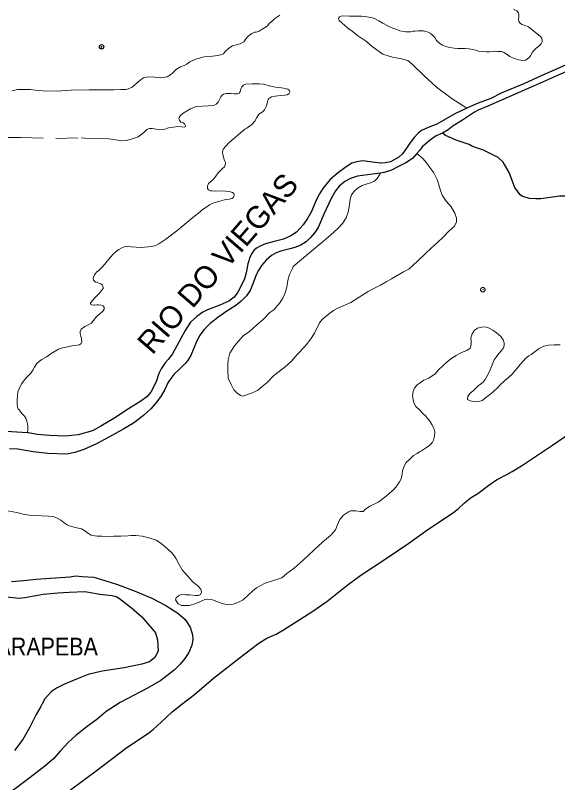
# Model space of a CAD drawing. Extents: x 267.7 to 296, y 7537.7 to 7565.8.
# Drawn here: x 280.408 to 282.842, y 7555.949 to 7559.393 of the extents above; entities that cross this region are included whole.
import ezdxf
from ezdxf.enums import TextEntityAlignment as Align

# ---------------------------------------------------------------- set-up
doc = ezdxf.new("R2010")
doc.units = 0
doc.header["$LTSCALE"] = 0.04
doc.header["$PDMODE"] = 32
doc.header["$PDSIZE"] = 0.02
doc.linetypes.add('SHORT_DASHED', pattern=[2.7, 1.5, -1.2])
for name, color, linetype, lineweight in [('1', 7, 'Continuous', 25), ('2', 7, 'Continuous', 25), ('21', 7, 'SHORT_DASHED', 13), ('7', 7, 'Continuous', 25)]:
    doc.layers.add(name, color=color, linetype=linetype, lineweight=lineweight)
doc.layers.add('54', color=7, linetype='Continuous')
doc.layers.add('61', color=7, linetype='Continuous')

msp = doc.modelspace()

# ---------------------------------------------------------------- linework, layer by layer
at = {"layer": '1'}
for points in [[(284.4547, 7559.8523), (284.377, 7559.8218), (284.2867, 7559.7831), (284.1184, 7559.7122), (283.9591, 7559.6438), (283.6289, 7559.4987), (283.5547, 7559.465), (283.1514, 7559.2873), (283.0583, 7559.2484), (282.7675, 7559.1216), (282.6934, 7559.0875), (282.5888, 7559.0438), (282.5414, 7559.0202), (282.4852, 7558.9986), (282.4399, 7558.9791), (282.4346, 7558.9766)], [(284.4569, 7559.8141), (284.4466, 7559.8195), (284.4404, 7559.8202), (284.422, 7559.8154), (284.324, 7559.7695), (284.0384, 7559.6483), (283.9549, 7559.6106), (283.5617, 7559.4394), (283.3631, 7559.3504), (282.9624, 7559.1771), (282.7741, 7559.0929), (282.5289, 7558.986), (282.4844, 7558.9668), (282.4686, 7558.9579), (282.4549, 7558.949), (282.4152, 7558.9223), (282.3734, 7558.8977), (282.3501, 7558.8792), (282.3251, 7558.8643)], [(282.4346, 7558.9766), (282.381, 7558.9507), (282.299, 7558.905), (282.2606, 7558.8897), (282.2301, 7558.8755), (282.2159, 7558.8645), (282.1981, 7558.8445), (282.1781, 7558.8188), (282.1633, 7558.7967), (282.146, 7558.772), (282.1292, 7558.7572), (282.105, 7558.7425), (282.0913, 7558.7362), (282.0682, 7558.7304), (282.0492, 7558.7294), (282.0466, 7558.7297)], [(282.3251, 7558.8643), (282.296, 7558.8525), (282.2714, 7558.8347), (282.2337, 7558.8025), (282.2227, 7558.7881), (282.2101, 7558.7735)], [(282.2101, 7558.7735), (282.1906, 7558.7511), (282.1611, 7558.7312), (282.1275, 7558.7141), (282.0954, 7558.6977), (282.0639, 7558.6881), (282.0608, 7558.6876)]]:
    msp.add_lwpolyline(points, dxfattribs=at)
at = {"layer": '2'}
msp.add_line((282.0608, 7558.6876), (282.0465, 7558.6854), dxfattribs=at)
for points in [[(282.0466, 7558.7297), (282.0208, 7558.7325), (281.9672, 7558.7399), (281.9404, 7558.7362), (281.9188, 7558.7294), (281.892, 7558.7131), (281.852, 7558.6826), (281.8189, 7558.6552), (281.7874, 7558.6163), (281.7726, 7558.5926), (281.7584, 7558.5637), (281.7369, 7558.5127), (281.719, 7558.4812), (281.6996, 7558.4533), (281.6701, 7558.4202), (281.6449, 7558.4033), (281.6117, 7558.3886), (281.5697, 7558.3776), (281.5302, 7558.3676), (281.5071, 7558.3576), (281.4903, 7558.3481), (281.4782, 7558.3371), (281.4687, 7558.3245), (281.4619, 7558.3108), (281.4519, 7558.2777), (281.444, 7558.2372), (281.4366, 7558.2109), (281.4256, 7558.1877), (281.4061, 7558.1504), (281.3893, 7558.1288), (281.3656, 7558.1104), (281.3262, 7558.092), (281.271, 7558.0715), (281.2489, 7558.0605), (281.2226, 7558.0416), (281.1947, 7558.0153), (281.1706, 7557.979), (281.1527, 7557.9459), (281.1127, 7557.8743), (281.0933, 7557.8486), (281.0801, 7557.8328), (281.0617, 7557.806), (281.0522, 7557.7849), (281.0417, 7557.7529), (281.0296, 7557.7266), (281.0165, 7557.7019), (280.9981, 7557.6814), (280.9707, 7557.6614), (280.915, 7557.6261), (280.8498, 7557.583), (280.7919, 7557.5494), (280.7536, 7557.5278), (280.6899, 7557.5099), (280.6337, 7557.5047), (280.5606, 7557.5068), (280.5064, 7557.512), (280.4671, 7557.5189), (280.4627, 7557.5192)], [(282.0465, 7558.6854), (282.0104, 7558.6799), (281.944, 7558.6716), (281.9125, 7558.6607), (281.8871, 7558.647), (281.8611, 7558.6264), (281.8454, 7558.6059), (281.8248, 7558.5703), (281.7919, 7558.5011), (281.7673, 7558.4415), (281.7522, 7558.4182), (281.733, 7558.3956), (281.7125, 7558.3765), (281.6892, 7558.3614), (281.6625, 7558.3504), (281.6392, 7558.3456), (281.6036, 7558.3367), (281.5783, 7558.3271), (281.557, 7558.3155), (281.5337, 7558.2936), (281.5146, 7558.2717), (281.5002, 7558.2504), (281.4892, 7558.2278), (281.4769, 7558.195), (281.4618, 7558.1573), (281.4447, 7558.134), (281.4214, 7558.11), (281.3974, 7558.0909), (281.3577, 7558.0655), (281.3166, 7558.0374), (281.2824, 7558.01), (281.2536, 7557.9813), (281.2379, 7557.9587), (281.2228, 7557.932), (281.2091, 7557.8991), (281.1954, 7557.8669), (281.181, 7557.8416), (281.1707, 7557.8306), (281.1454, 7557.8059), (281.1187, 7557.7806), (281.1057, 7557.7635), (281.092, 7557.7429), (281.0783, 7557.7135), (281.0618, 7557.6854), (281.0434, 7557.658), (281.0153, 7557.6272), (280.9824, 7557.597), (280.9386, 7557.5621), (280.8954, 7557.5368), (280.8475, 7557.5107), (280.7728, 7557.4697), (280.716, 7557.445), (280.6742, 7557.4306), (280.6393, 7557.4238), (280.553, 7557.4258), (280.4872, 7557.434), (280.4187, 7557.4457), (280.3811, 7557.4477)], [(280.6026, 7555.8775), (280.7073, 7555.9548), (280.7711, 7556.0022), (280.908, 7556.1063), (281.0057, 7556.1707), (281.0286, 7556.1888), (281.0608, 7556.2181), (281.1111, 7556.2667), (281.1544, 7556.3012), (281.2123, 7556.3439), (281.2978, 7556.4171), (281.4324, 7556.5218), (281.5014, 7556.5751), (281.5371, 7556.5967), (281.5786, 7556.6149), (281.6108, 7556.6353), (281.7384, 7556.7161), (281.8063, 7556.7623), (281.8952, 7556.8343), (281.9578, 7556.8794), (282.072, 7556.9554), (282.1732, 7557.0245), (282.2598, 7557.0848), (282.3704, 7557.1579), (282.3956, 7557.1772), (282.4237, 7557.2041), (282.4541, 7557.2287), (282.4833, 7557.2463), (282.5325, 7557.2849), (282.5676, 7557.3083), (282.6133, 7557.3323), (282.6378, 7557.3452), (282.6794, 7557.3703), (282.8181, 7557.464), (283.0802, 7557.643)], [(280.4627, 7557.5192), (280.3899, 7557.5242), (280.3547, 7557.5253), (280.3201, 7557.5194), (280.287, 7557.5093), (280.2588, 7557.4933), (280.2322, 7557.4741), (280.2055, 7557.4464), (280.165, 7557.3889), (280.1086, 7557.3074), (280.0956, 7557.2871), (280.0755, 7557.2557)], [(280.3913, 7556.8522), (280.4447, 7556.856), (280.5009, 7556.8616), (280.6527, 7556.8729), (280.6799, 7556.8766), (280.708, 7556.8747), (280.7595, 7556.871), (280.8092, 7556.8569), (280.8663, 7556.8382), (280.946, 7556.8082), (281.0209, 7556.7764), (281.0828, 7556.7445), (281.1371, 7556.7098), (281.1699, 7556.6817), (281.1924, 7556.6461), (281.2036, 7556.6124), (281.2045, 7556.5918), (281.1999, 7556.5656), (281.1867, 7556.5337), (281.1689, 7556.5065), (281.1474, 7556.4812), (281.1212, 7556.4541), (281.0603, 7556.4072), (281.0003, 7556.3726), (280.8785, 7556.3079), (280.8148, 7556.2676), (280.7736, 7556.232), (280.7295, 7556.2002), (280.679, 7556.1599), (280.6471, 7556.1308), (280.6087, 7556.0906), (280.5787, 7556.055), (280.5403, 7556.0222), (280.4747, 7555.9725), (280.3792, 7555.8994)], [(280.3677, 7556.7835), (280.424, 7556.7774), (280.4501, 7556.7804), (280.5334, 7556.7945), (280.5987, 7556.8005), (280.6489, 7556.8035), (280.7192, 7556.8066), (280.7544, 7556.8015), (280.7875, 7556.7955), (280.8136, 7556.7925), (280.8428, 7556.7885), (280.8598, 7556.7845), (280.8749, 7556.7754), (280.9291, 7556.7342), (280.9753, 7556.6931), (281.0115, 7556.6519), (281.0296, 7556.6308), (281.0366, 7556.6208), (281.0456, 7556.5906), (281.0486, 7556.5384), (281.0346, 7556.5103), (281.0105, 7556.4912), (280.9763, 7556.4802), (280.897, 7556.4641), (280.7976, 7556.449), (280.7343, 7556.434), (280.6831, 7556.4129), (280.6288, 7556.3908), (280.5927, 7556.3727), (280.5706, 7556.3576), (280.5545, 7556.3416), (280.5405, 7556.3245), (280.5284, 7556.3024), (280.5224, 7556.2913), (280.5013, 7556.2542), (280.4732, 7556.1979), (280.442, 7556.1427), (280.4039, 7556.0925)]]:
    msp.add_lwpolyline(points, dxfattribs=at)
at = {"layer": '21'}
for points in [[(280.3935, 7559.0548), (280.4182, 7559.06), (280.4466, 7559.0609), (280.4741, 7559.0604), (280.4964, 7559.0576), (280.5291, 7559.0548), (280.5945, 7559.0533), (280.658, 7559.0567), (280.7386, 7559.0585), (280.7869, 7559.0581), (280.8239, 7559.0581), (280.8495, 7559.0595), (280.8808, 7559.06), (280.905, 7559.0609), (280.9182, 7559.0647), (280.9315, 7559.0709), (280.9415, 7559.0789), (280.9576, 7559.0932), (280.9737, 7559.1064), (280.9837, 7559.1121), (281.0045, 7559.1164), (281.0329, 7559.1159), (281.0595, 7559.1121), (281.0894, 7559.1169), (281.1045, 7559.1254), (281.1145, 7559.1344), (281.1315, 7559.151), (281.1486, 7559.1619), (281.1661, 7559.168), (281.1775, 7559.1733), (281.1908, 7559.1842), (281.2079, 7559.1922), (281.2178, 7559.197), (281.2548, 7559.2064), (281.2927, 7559.2102), (281.3164, 7559.2126), (281.3344, 7559.2169), (281.3415, 7559.2211), (281.3491, 7559.2306), (281.3662, 7559.2458), (281.3832, 7559.2567), (281.4055, 7559.2619), (281.4169, 7559.2647), (281.434, 7559.2737), (281.4401, 7559.2828), (281.4496, 7559.296), (281.4581, 7559.3046), (281.4686, 7559.3121), (281.4818, 7559.3174), (281.4894, 7559.3183), (281.5022, 7559.3221), (281.5155, 7559.3316), (281.5382, 7559.3453), (281.5491, 7559.3576), (281.5619, 7559.369), (281.5724, 7559.3794), (281.5956, 7559.3941)], [(282.4346, 7558.9766), (282.369, 7559.0187), (282.2981, 7559.0713), (282.2422, 7559.1221), (282.1885, 7559.1746), (282.169, 7559.1901), (282.1411, 7559.1981), (282.1005, 7559.2049), (282.0851, 7559.2106), (282.0571, 7559.2186), (282.0417, 7559.2289), (282.0091, 7559.2529), (281.98, 7559.2786), (281.9428, 7559.3032), (281.92, 7559.3226), (281.9, 7559.3357), (281.8863, 7559.3472), (281.8737, 7559.3591), (281.8612, 7559.3694), (281.86, 7559.3734), (281.8589, 7559.3791), (281.86, 7559.3826), (281.8634, 7559.3871), (281.8703, 7559.3894), (281.8772, 7559.3906), (281.908, 7559.39), (281.9617, 7559.39), (281.9857, 7559.3871), (282.004, 7559.3837), (282.0205, 7559.3791), (282.04, 7559.3689), (282.0577, 7559.3574), (282.0851, 7559.3432), (282.1028, 7559.3357), (282.1205, 7559.3289), (282.1331, 7559.3243), (282.1496, 7559.3209), (282.1605, 7559.3197), (282.1719, 7559.3197), (282.1822, 7559.3197), (282.193, 7559.322), (282.2028, 7559.3226), (282.2147, 7559.3232), (282.2399, 7559.3237), (282.2564, 7559.3197), (282.2702, 7559.3129), (282.2822, 7559.3026), (282.2901, 7559.294), (282.2987, 7559.2797), (282.313, 7559.2672), (282.3244, 7559.2598), (282.3398, 7559.2535), (282.3587, 7559.2483), (282.3775, 7559.2455), (282.3935, 7559.2443), (282.4141, 7559.2443), (282.4272, 7559.2438), (282.4432, 7559.2426), (282.4615, 7559.2403), (282.4747, 7559.2363), (282.4866, 7559.2323), (282.5032, 7559.2306), (282.5204, 7559.2301), (282.5358, 7559.2295), (282.5518, 7559.2306), (282.5649, 7559.2318), (282.574, 7559.2306), (282.5895, 7559.2306), (282.6003, 7559.2266), (282.6152, 7559.2169), (282.6277, 7559.2078), (282.646, 7559.1998), (282.6683, 7559.1929), (282.6849, 7559.1906), (282.6974, 7559.1923), (282.7054, 7559.1963), (282.714, 7559.2032), (282.7203, 7559.2112), (282.7294, 7559.2272), (282.7357, 7559.2358), (282.7448, 7559.2455), (282.7574, 7559.2552), (282.7677, 7559.266), (282.7717, 7559.274), (282.7723, 7559.2797), (282.7705, 7559.2906), (282.7654, 7559.2975), (282.7408, 7559.3174), (282.7203, 7559.334), (282.7117, 7559.3409), (282.6951, 7559.3477), (282.6809, 7559.3523), (282.6734, 7559.3574), (282.6672, 7559.3654), (282.6654, 7559.3751)], [(282.6654, 7559.3751), (282.6672, 7559.3866), (282.6683, 7559.3951), (282.666, 7559.4048), (282.658, 7559.4134), (282.6443, 7559.4214)], [(280.3509, 7558.8446), (280.4331, 7558.8451), (280.5894, 7558.8402), (280.704, 7558.8435), (280.7358, 7558.8402), (280.8257, 7558.8391), (280.8684, 7558.8331), (280.8865, 7558.8303), (280.9052, 7558.8314), (280.9227, 7558.8364), (280.9589, 7558.8473), (280.971, 7558.8567), (280.9847, 7558.8676), (280.9973, 7558.8813), (281.0093, 7558.8852), (281.0225, 7558.8852), (281.04, 7558.8824), (281.0696, 7558.8808), (281.079, 7558.8819), (281.0954, 7558.8879), (281.1173, 7558.8917), (281.1371, 7558.8939), (281.1541, 7558.8923), (281.1656, 7558.8906), (281.1705, 7558.8934), (281.1716, 7558.8978), (281.1672, 7558.9055), (281.1607, 7558.9109), (281.1513, 7558.9142), (281.1442, 7558.9219), (281.142, 7558.9285), (281.1437, 7558.9345), (281.148, 7558.9427), (281.1612, 7558.9537), (281.1766, 7558.9625), (281.1941, 7558.9734), (281.2193, 7558.9833), (281.2473, 7558.986), (281.2983, 7558.9882), (281.3098, 7558.9948), (281.3185, 7559.0041), (281.324, 7559.0151), (281.3295, 7559.0272), (281.3344, 7559.0337), (281.3416, 7559.0387), (281.3547, 7559.042), (281.3745, 7559.0425), (281.3898, 7559.0414), (281.4052, 7559.0409), (281.4117, 7559.0431), (281.4167, 7559.0502), (281.4178, 7559.0573), (281.4194, 7559.0639), (281.4244, 7559.0727), (281.4326, 7559.0803), (281.4424, 7559.0842), (281.4726, 7559.0858), (281.5022, 7559.0858), (281.5219, 7559.0836), (281.5378, 7559.0803), (281.5472, 7559.076), (281.5757, 7559.0705), (281.5899, 7559.0699), (281.6025, 7559.0683), (281.6201, 7559.065), (281.631, 7559.0622), (281.6376, 7559.0562), (281.6393, 7559.0502), (281.6354, 7559.0414), (281.6283, 7559.0365), (281.6157, 7559.0343), (281.5981, 7559.0332), (281.5746, 7559.0304), (281.557, 7559.0272), (281.5444, 7559.0178), (281.5395, 7559.0069), (281.5346, 7558.9871), (281.5263, 7558.9696), (281.5159, 7558.9581), (281.5011, 7558.9499), (281.4912, 7558.9351), (281.4825, 7558.9181)], [(281.4825, 7558.9181), (281.4688, 7558.9027), (281.4474, 7558.8868), (281.4375, 7558.8819), (281.3657, 7558.8216), (281.341, 7558.7925)], [(281.341, 7558.7925), (281.3388, 7558.7859), (281.3377, 7558.7783), (281.3394, 7558.7695), (281.3427, 7558.7569), (281.3471, 7558.7421), (281.3509, 7558.7322), (281.3503, 7558.7201), (281.3471, 7558.7136), (281.3372, 7558.7059), (281.3196, 7558.6878), (281.3103, 7558.6763), (281.2983, 7558.6593), (281.2857, 7558.6478), (281.2747, 7558.6379), (281.2698, 7558.6264), (281.2708, 7558.6154), (281.2747, 7558.61), (281.284, 7558.6061), (281.2911, 7558.6056), (281.3059, 7558.6045), (281.3295, 7558.605), (281.3509, 7558.6045), (281.3673, 7558.6017), (281.3832, 7558.5973), (281.3882, 7558.593), (281.3904, 7558.5842), (281.3887, 7558.5782), (281.3865, 7558.5754), (281.3794, 7558.5716), (281.3673, 7558.5683), (281.3465, 7558.565), (281.3262, 7558.559), (281.2988, 7558.5513), (281.2791, 7558.542), (281.2621, 7558.5305), (281.2473, 7558.5222), (281.2369, 7558.5118), (281.2051, 7558.485), (281.1327, 7558.4257), (281.0834, 7558.3885), (281.0526, 7558.3671), (281.0378, 7558.36), (281.0187, 7558.3556), (280.9732, 7558.3517), (280.9277, 7558.3545), (280.9118, 7558.3561), (280.8964, 7558.3539), (280.8821, 7558.3479), (280.8723, 7558.3419), (280.8624, 7558.3342), (280.8454, 7558.3199), (280.8361, 7558.309), (280.8196, 7558.2898), (280.8087, 7558.275), (280.7961, 7558.2607), (280.7835, 7558.2498), (280.7714, 7558.2399), (280.7632, 7558.2284), (280.7588, 7558.218), (280.7571, 7558.2097), (280.7588, 7558.2037), (280.7626, 7558.1999), (280.7692, 7558.196), (280.7758, 7558.1938), (280.7911, 7558.1884), (280.7983, 7558.1834), (280.8027, 7558.1736), (280.8016, 7558.1664), (280.7955, 7558.1588), (280.7879, 7558.1505), (280.7835, 7558.145), (280.7681, 7558.1286), (280.7528, 7558.1116), (280.7495, 7558.1078), (280.7456, 7558.1028), (280.7467, 7558.0957), (280.7517, 7558.093), (280.7599, 7558.0919), (280.7637, 7558.0924), (280.773, 7558.0935), (280.7807, 7558.0941), (280.7928, 7558.0924), (280.8021, 7558.0886), (280.8059, 7558.0836), (280.8059, 7558.0738), (280.8021, 7558.0672), (280.7857, 7558.0518), (280.7725, 7558.042), (280.7599, 7558.0255), (280.7478, 7558.0113), (280.738, 7558.0052), (280.7204, 7557.997), (280.7029, 7557.9844), (280.699, 7557.9745)], [(281.4282, 7557.6841), (281.4673, 7557.6978), (281.4948, 7557.7094), (281.5149, 7557.7252), (281.5391, 7557.7464), (281.5687, 7557.777), (281.6173, 7557.814), (281.6479, 7557.8414), (281.6733, 7557.87), (281.7092, 7557.908), (281.7335, 7557.9407), (281.7504, 7557.9671), (281.7726, 7558.0126), (281.7853, 7558.0284), (281.8127, 7558.0516), (281.836, 7558.0685), (281.855, 7558.0791), (281.9131, 7558.1044), (281.9511, 7558.1287), (281.9912, 7558.153), (282.0166, 7558.1668), (282.0462, 7558.1816), (282.0715, 7558.1963), (282.0958, 7558.2111), (282.1497, 7558.2418), (282.174, 7558.2544), (282.213, 7558.2904), (282.2479, 7558.3231), (282.2764, 7558.3495), (282.3028, 7558.3738), (282.3282, 7558.3981), (282.3525, 7558.4234), (282.3789, 7558.4467), (282.3884, 7558.4657), (282.3884, 7558.4826), (282.3799, 7558.5058), (282.3641, 7558.5333), (282.3409, 7558.5597), (282.3229, 7558.5861), (282.3166, 7558.6062), (282.3092, 7558.6326), (282.3007, 7558.6558), (282.2859, 7558.6865), (282.268, 7558.7108), (282.2532, 7558.7308), (282.2373, 7558.7498), (282.2101, 7558.7735)], [(282.0465, 7558.6854), (282.0324, 7558.6611), (282.0198, 7558.6495), (282.0018, 7558.641), (281.9828, 7558.6347), (281.9648, 7558.6294), (281.9458, 7558.6189), (281.931, 7558.6062), (281.9173, 7558.5872), (281.911, 7558.5682), (281.9078, 7558.5428), (281.9014, 7558.509), (281.893, 7558.4837), (281.8761, 7558.4583), (281.8571, 7558.4372), (281.837, 7558.4192), (281.8117, 7558.3981), (281.7842, 7558.3738), (281.7208, 7558.321), (281.6543, 7558.2661), (281.6501, 7558.2544), (281.6384, 7558.2291), (281.631, 7558.2027), (281.6258, 7558.1731), (281.6152, 7558.1383), (281.6067, 7558.1214), (281.5951, 7558.1023), (281.5687, 7558.0717), (281.5508, 7558.059), (281.5201, 7558.0284), (281.4916, 7558.0041), (281.4578, 7557.9724), (281.4325, 7557.9555), (281.4092, 7557.9312), (281.3913, 7557.909), (281.3712, 7557.8763), (281.3638, 7557.8467), (281.3617, 7557.8256), (281.3617, 7557.7981), (281.3638, 7557.7643), (281.3765, 7557.7358), (281.3892, 7557.7126), (281.4039, 7557.6967), (281.4187, 7557.6862), (281.4282, 7557.6841)], [(281.4305, 7556.769), (281.4563, 7556.793), (281.473, 7556.8087), (281.4896, 7556.8235), (281.5062, 7556.8318), (281.5293, 7556.8448), (281.5672, 7556.8558), (281.6042, 7556.8679), (281.6264, 7556.8882), (281.6596, 7556.9113), (281.6864, 7556.9362), (281.7169, 7556.964), (281.7502, 7556.9954), (281.7844, 7557.0268), (281.8232, 7557.0601), (281.8454, 7557.0841), (281.8528, 7557.1035), (281.8648, 7557.1294), (281.8814, 7557.1488), (281.9027, 7557.1645), (281.9128, 7557.1691), (281.9359, 7557.1691), (281.9553, 7557.1654), (281.9683, 7557.1663), (281.9738, 7557.17), (281.9757, 7557.1728), (281.9988, 7557.1894), (282.0367, 7557.2079), (282.0468, 7557.2153), (282.0736, 7557.2356), (282.0977, 7557.2569), (282.106, 7557.2652), (282.1198, 7557.2819), (282.1318, 7557.2994), (282.1392, 7557.3133), (282.1439, 7557.3336), (282.1448, 7557.3484), (282.1512, 7557.3669), (282.1623, 7557.3853), (282.1771, 7557.4001), (282.1947, 7557.4168), (282.2113, 7557.4269), (282.2215, 7557.4334), (282.2307, 7557.438), (282.2538, 7557.4537), (282.2677, 7557.4639), (282.2806, 7557.4778), (282.2852, 7557.4861), (282.2889, 7557.5036), (282.2899, 7557.5221), (282.2862, 7557.5397), (282.2778, 7557.5572), (282.2677, 7557.5711), (282.2483, 7557.5951), (282.2363, 7557.6062), (282.2215, 7557.6219), (282.2058, 7557.6376), (282.1965, 7557.6543), (282.1928, 7557.6681), (282.1901, 7557.6848), (282.1928, 7557.7051), (282.1993, 7557.7199), (282.2104, 7557.7328), (282.2261, 7557.7457), (282.2418, 7557.7559), (282.2631, 7557.7651), (282.2926, 7557.7836), (282.3093, 7557.803), (282.3287, 7557.8206), (282.3444, 7557.8363), (282.3629, 7557.8511), (282.3869, 7557.8668), (282.4109, 7557.8797), (282.4349, 7557.889), (282.4497, 7557.8991), (282.4543, 7557.9158), (282.4534, 7557.9324), (282.4525, 7557.9453), (282.458, 7557.9638), (282.4682, 7557.9805), (282.4821, 7557.9888), (282.4996, 7557.9934), (282.5163, 7557.9943), (282.532, 7557.9897), (282.5514, 7557.9805), (282.568, 7557.9684), (282.5865, 7557.9509), (282.5967, 7557.937), (282.6013, 7557.9232), (282.6022, 7557.9112), (282.5985, 7557.901), (282.5893, 7557.889), (282.5772, 7557.8751), (282.5652, 7557.8585), (282.5569, 7557.8474)], [(280.699, 7557.9745), (280.699, 7557.9647), (280.7018, 7557.9532), (280.7051, 7557.94), (280.7062, 7557.9257), (280.7029, 7557.9197)], [(280.7029, 7557.9197), (280.6957, 7557.9148), (280.6848, 7557.9126), (280.6612, 7557.9093), (280.642, 7557.9055), (280.619, 7557.9005), (280.602, 7557.894), (280.5861, 7557.8852), (280.5691, 7557.8759), (280.5554, 7557.8654), (280.5483, 7557.86), (280.5269, 7557.849), (280.517, 7557.8413), (280.5033, 7557.8282), (280.4945, 7557.8139), (280.4869, 7557.8008), (280.4775, 7557.787), (280.4611, 7557.7711), (280.4485, 7557.7569), (280.437, 7557.7404), (280.4277, 7557.7234), (280.4194, 7557.7032), (280.4178, 7557.6856), (280.4167, 7557.6681), (280.4161, 7557.6494), (280.4183, 7557.6341), (280.4205, 7557.627), (280.426, 7557.6204), (280.4304, 7557.6138), (280.4397, 7557.6028), (280.449, 7557.5941), (280.4556, 7557.5842), (280.4595, 7557.5716), (280.4627, 7557.559), (280.4644, 7557.5486), (280.4644, 7557.5343), (280.4627, 7557.5192)], [(282.495, 7557.7374), (282.4858, 7557.73), (282.4636, 7557.7097), (282.4479, 7557.6958), (282.4386, 7557.682), (282.4377, 7557.6718), (282.4377, 7557.669), (282.4488, 7557.6626), (282.4728, 7557.658), (282.4876, 7557.6598), (282.5024, 7557.6644), (282.5237, 7557.6801), (282.5431, 7557.6949), (282.5532, 7557.7042), (282.5736, 7557.7226), (282.5819, 7557.7337), (282.605, 7557.7541), (282.6216, 7557.767), (282.6392, 7557.7836), (282.6512, 7557.7984), (282.6623, 7557.8104), (282.6734, 7557.8261), (282.6881, 7557.8428), (282.6983, 7557.8529), (282.7131, 7557.864), (282.7233, 7557.8714), (282.7593, 7557.8982), (282.7796, 7557.9075), (282.8009, 7557.913), (282.8258, 7557.9148), (282.8526, 7557.9148)], [(282.5569, 7557.8474), (282.5394, 7557.8021), (282.5283, 7557.779), (282.5172, 7557.7578), (282.5079, 7557.7467), (282.495, 7557.7374)], [(280.365, 7557.17), (280.414, 7557.1608), (280.4426, 7557.1543), (280.4703, 7557.1488), (280.5258, 7557.1469), (280.5572, 7557.1451), (280.5785, 7557.1432), (280.5932, 7557.1377), (280.6117, 7557.1275), (280.6265, 7557.1155), (280.6404, 7557.1063), (280.6515, 7557.1017), (280.6653, 7557.097), (280.6838, 7557.0933), (280.7041, 7557.0887), (280.7198, 7557.0795), (280.7282, 7557.0712), (280.7485, 7557.0591), (280.7642, 7557.0564), (280.7744, 7557.0545), (280.7956, 7557.0545), (280.8187, 7557.0527), (280.8492, 7557.0545), (280.8816, 7557.0545), (280.913, 7557.0573), (280.9278, 7557.0582), (280.9481, 7557.0582), (280.9777, 7557.0555), (281.0072, 7557.0471), (281.0396, 7557.0379), (281.0562, 7557.0268), (281.0784, 7557.0092), (281.108, 7556.9824), (281.1227, 7556.9649), (281.1301, 7556.9529), (281.1449, 7556.9252), (281.1569, 7556.9039), (281.1671, 7556.8919), (281.1819, 7556.8762), (281.1902, 7556.866), (281.2031, 7556.8522), (281.2142, 7556.8429), (281.229, 7556.8309), (281.241, 7556.817), (281.2429, 7556.8041), (281.2383, 7556.793), (281.2299, 7556.7893), (281.2161, 7556.7884), (281.1911, 7556.7912), (281.1717, 7556.7921), (281.1514, 7556.793), (281.1412, 7556.7893), (281.1292, 7556.7782), (281.1264, 7556.769), (281.1394, 7556.7514), (281.1542, 7556.744), (281.168, 7556.744), (281.1884, 7556.744), (281.2087, 7556.7505), (281.2336, 7556.7588), (281.2456, 7556.7653), (281.2586, 7556.7708), (281.2715, 7556.7727), (281.2863, 7556.7708), (281.2974, 7556.7681), (281.3159, 7556.7607), (281.3399, 7556.7514)], [(281.3399, 7556.7514), (281.3676, 7556.7477), (281.3852, 7556.7496), (281.4064, 7556.757), (281.4305, 7556.769)]]:
    msp.add_lwpolyline(points, dxfattribs=at)
msp.add_point((282.5061, 7558.1614), dxfattribs=at)
at = {"layer": '54'}
msp.add_point((280.795, 7559.2521), dxfattribs=at)
at = {"layer": '7'}
msp.add_lwpolyline([(283.077, 7558.529), (283.003, 7558.5583), (282.9447, 7558.5737), (282.8926, 7558.5819), (282.8509, 7558.5821), (282.7671, 7558.5695), (282.7442, 7558.5701), (282.7155, 7558.5708), (282.6838, 7558.5794), (282.6732, 7558.5873), (282.6502, 7558.6206), (282.6238, 7558.6878), (282.5966, 7558.7335), (282.575, 7558.7552), (282.5084, 7558.7876), (282.4598, 7558.804), (282.4443, 7558.8139), (282.3861, 7558.8329), (282.3387, 7558.8541), (282.3251, 7558.8643)], dxfattribs=at)

# ---------------------------------------------------------------- texts
at = {"layer": '54', "width": 0.9}
msp.add_text('ILHA CARAPEBA', height=0.08, dxfattribs=at).set_placement((280.0132, 7556.5196))
at = {"layer": '61'}
msp.add_text('RIO DO VIEGAS', height=0.1, rotation=49.086, dxfattribs=at).set_placement((281.3537, 7558.2471), align=Align.CENTER)

doc.saveas('drawing.dxf')
